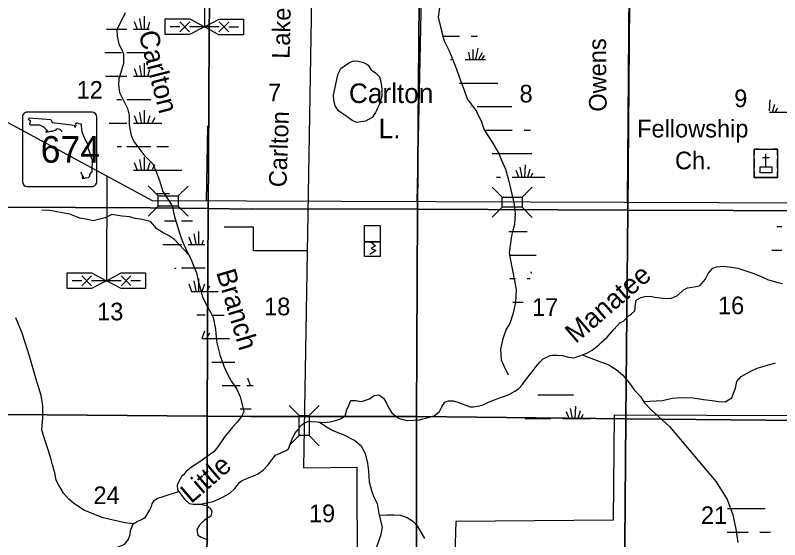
# Model space of a CAD drawing. Extents: x 380424 to 701066, y 1117407 to 1412949.
# Drawn here: x 569307 to 588826, y 1217069 to 1230454 of the extents above; entities that cross this region are included whole.
import ezdxf

# ---------------------------------------------------------------- set-up
doc = ezdxf.new("R2010")
doc.units = 0
for name, color, linetype in [('Bridges', 7, 'Continuous'), ('Bridges and Drawbridges Local Roads', 7, 'Continuous'), ('Bridges and Drawbridges State Highways', 7, 'Continuous'), ('Culture', 7, 'Continuous'), ('Culture Text', 7, 'Continuous'), ('Lakes and Ponds', 7, 'Continuous'), ('Lakes and Ponds Text', 7, 'Continuous'), ('Local Roads Improved', 7, 'Continuous'), ('Local Roads Paved', 7, 'Continuous'), ('Local Roads Related Cells', 7, 'Continuous'), ('Local Roads Related Text', 7, 'Continuous'), ('Narrow Canals', 7, 'Continuous'), ('Narrow River Creek and Branch and Slough', 7, 'Continuous'), ('Narrow River Creek and Branch and Slough Text', 7, 'Continuous'), ('Roadshilelds State Highways', 7, 'Continuous'), ('Section Lines', 7, 'Continuous'), ('Section Numbers', 7, 'Continuous'), ('State Routes Highway Center Lines', 7, 'Continuous'), ('Swamps', 7, 'Continuous'), ('Township  and Range lines', 7, 'Continuous')]:
    doc.layers.add(name, color=color, linetype=linetype)

msp = doc.modelspace()

# ---------------------------------------------------------------- linework, layer by layer
at = {"layer": 'Bridges'}
msp.add_line((576554, 1219728), (576296, 1219473), dxfattribs=at)
at = {"layer": 'Bridges and Drawbridges Local Roads'}
for p, q in [((576557, 1220240), (576302, 1220497)), ((576813, 1220239), (577070, 1220493)), ((576810, 1219727), (577064, 1219469))]:
    msp.add_line(p, q, dxfattribs=at)
msp.add_lwpolyline([(576554, 1219728), (576557, 1220240), (576813, 1220239), (576810, 1219727)], close=True, dxfattribs=at)
at = {"layer": 'Bridges and Drawbridges State Highways'}
for p, q in [((572955, 1225842), (572699, 1226099)), ((573467, 1225842), (573723, 1226097)), ((581739, 1225813), (581484, 1226070)), ((582251, 1225810), (582508, 1226065)), ((572954, 1225586), (572698, 1225331)), ((573466, 1225586), (573722, 1225329)), ((581737, 1225557), (581480, 1225302)), ((582249, 1225554), (582504, 1225297))]:
    msp.add_line(p, q, dxfattribs=at)
for points in [[(572955, 1225842), (573467, 1225842), (573466, 1225586), (572954, 1225586)], [(581739, 1225813), (582251, 1225810), (582249, 1225554), (581737, 1225557)]]:
    msp.add_lwpolyline(points, close=True, dxfattribs=at)
at = {"layer": 'Culture'}
for p, q in [((588173, 1227034), (588173, 1226884)), ((588293, 1227034), (588173, 1227034)), ((588383, 1227034), (588563, 1227034)), ((588773, 1227034), (588653, 1227034)), ((588773, 1226884), (588773, 1227034)), ((588173, 1226794), (588173, 1226554)), ((588383, 1226824), (588563, 1226824)), ((588473, 1226584), (588473, 1226914)), ((588773, 1226554), (588773, 1226794)), ((588173, 1226464), (588173, 1226314)), ((588773, 1226314), (588773, 1226464)), ((588173, 1226314), (588773, 1226314)), ((578226, 1224297), (578226, 1224668)), ((578226, 1224668), (578626, 1224668)), ((578626, 1224668), (578626, 1224297)), ((578626, 1224297), (578226, 1224297))]:
    msp.add_line(p, q, dxfattribs=at)
for points in [[(588173, 1227034), (588773, 1227034), (588773, 1226314), (588173, 1226314)], [(588323, 1226584), (588623, 1226584), (588623, 1226434), (588323, 1226434)], [(578626, 1224668), (578226, 1224668), (578226, 1225087), (578626, 1225087)]]:
    msp.add_lwpolyline(points, close=True, dxfattribs=at)
msp.add_lwpolyline([(578382, 1224668), (578503, 1224574), (578391, 1224506), (578511, 1224447), (578356, 1224347)], dxfattribs=at)
at = {"layer": 'Lakes and Ponds'}
msp.add_lwpolyline([(578506, 1227976), (578505, 1227974), (578416, 1227848), (578248, 1227749), (578022, 1227722), (577906, 1227770), (577744, 1227885), (577570, 1228011), (577476, 1228142), (577439, 1228284), (577434, 1228415), (577460, 1228536), (577518, 1228814), (577555, 1228956), (577618, 1229098), (577702, 1229156), (577843, 1229245), (577943, 1229292), (578059, 1229287), (578195, 1229250), (578284, 1229203), (578316, 1229177), (578395, 1229066), (578505, 1228982), (578599, 1228893), (578610, 1228885)], dxfattribs=at)
msp.add_spline([(578610, 1228885), (578663, 1228397), (578506, 1227976)], degree=3, dxfattribs=at)
at = {"layer": 'Local Roads Improved'}
msp.add_line((574192, 1225711), (574222, 1227633), dxfattribs=at)
for points in [[(574168, 1234761), (574134, 1230158)], [(576757, 1224443), (575392, 1224441), (575391, 1225044), (574642, 1225050)]]:
    msp.add_lwpolyline(points, dxfattribs=at)
at = {"layer": 'Local Roads Paved'}
msp.add_line((571645, 1226344), (571632, 1223677), dxfattribs=at)
for points in [[(576809, 1246604), (576867, 1230903), (576662, 1218901), (578027, 1218917), (578037, 1216197), (580511, 1216138)], [(584939, 1225673), (585048, 1239741)], [(579568, 1225692), (579680, 1230941), (579637, 1236122), (576848, 1236202)], [(594146, 1225641), (594030, 1220213), (584600, 1220250), (584573, 1217567), (580552, 1217530), (580478, 1214990), (581912, 1214974), (581785, 1204105)]]:
    msp.add_lwpolyline(points, dxfattribs=at)
at = {"layer": 'Local Roads Related Cells'}
for p, q in [((573133, 1229963), (573135, 1230363)), ((573135, 1230363), (573760, 1230360)), ((573508, 1230036), (573760, 1230285)), ((573758, 1230035), (573510, 1230286)), ((573760, 1230360), (574134, 1230158)), ((574134, 1230158), (574510, 1230356)), ((574508, 1230031), (574760, 1230280)), ((574510, 1230356), (575135, 1230353)), ((574758, 1230032), (574510, 1230283)), ((575135, 1230353), (575133, 1229953)), ((573509, 1230161), (573259, 1230162)), ((574134, 1230158), (573758, 1229960)), ((574509, 1230156), (573759, 1230160)), ((574508, 1229956), (574134, 1230158)), ((575009, 1230154), (574759, 1230155)), ((573758, 1229960), (573133, 1229963)), ((575133, 1229953), (574508, 1229956)), ((570632, 1223877), (571257, 1223877)), ((570632, 1223477), (570632, 1223877)), ((571257, 1223877), (571632, 1223677)), ((571632, 1223677), (572007, 1223877)), ((572007, 1223877), (572632, 1223877)), ((572632, 1223877), (572632, 1223477)), ((571007, 1223677), (570757, 1223677)), ((571007, 1223552), (571257, 1223802)), ((571257, 1223552), (571007, 1223802)), ((571632, 1223677), (571257, 1223477)), ((572007, 1223677), (571257, 1223677)), ((572007, 1223477), (571632, 1223677)), ((572257, 1223555), (572007, 1223805)), ((572007, 1223552), (572257, 1223802)), ((572507, 1223677), (572257, 1223677)), ((571257, 1223477), (570632, 1223477)), ((572632, 1223477), (572007, 1223477))]:
    msp.add_line(p, q, dxfattribs=at)
at = {"layer": 'Narrow Canals'}
msp.add_lwpolyline([(580156, 1230771), (580104, 1230404), (580161, 1230157), (580256, 1229800), (580382, 1229543), (580497, 1229275), (580576, 1229076), (580644, 1228881), (580765, 1228545), (580844, 1228325), (581075, 1228015), (581211, 1227732), (581280, 1227532), (581485, 1227217), (581653, 1226928), (581716, 1226776), (581826, 1226529), (581899, 1226251), (581973, 1225925), (582036, 1225668), (582067, 1225406), (582057, 1225112), (581999, 1224928), (581973, 1224828), (581920, 1224387), (581968, 1224109), (582010, 1223894), (582094, 1223453), (582078, 1223122), (582015, 1222822), (581931, 1222591), (581842, 1222439), (581752, 1222198), (581700, 1221930), (581716, 1221657), (581784, 1221510), (581894, 1221274)], dxfattribs=at)
at = {"layer": 'Narrow River Creek and Branch and Slough'}
for points in [[(572112, 1230519), (571996, 1230266), (571901, 1230093), (571907, 1229924), (571954, 1229719), (572012, 1229604), (572070, 1229467), (572070, 1229225), (572028, 1229078), (571954, 1228831), (571944, 1228673), (571965, 1228484), (572049, 1228316), (572175, 1228079), (572212, 1227906), (572217, 1227658), (572264, 1227385), (572333, 1227233), (572590, 1226891), (572822, 1226660), (572911, 1226444), (572985, 1226239), (573073, 1225955), (573311, 1225587), (573317, 1225561), (573354, 1225387), (573390, 1225256), (573459, 1225035), (573527, 1224825), (573580, 1224683), (573690, 1224431), (573790, 1224241), (573853, 1224089), (573932, 1223879), (573979, 1223679), (574032, 1223463), (574090, 1223258), (574216, 1223011), (574295, 1222874), (574358, 1222738), (574416, 1222443), (574437, 1222228), (574452, 1222096), (574526, 1221791), (574636, 1221497), (574715, 1221308), (574826, 1221103), (574962, 1220913), (575052, 1220714), (575120, 1220451), (575141, 1220330), (575083, 1220214), (574973, 1220072), (574852, 1219941), (574752, 1219815), (574663, 1219709), (574568, 1219567), (574479, 1219436), (574373, 1219310), (574263, 1219236), (574116, 1219126), (573995, 1219042), (573879, 1218968), (573795, 1218916), (573674, 1218810), (573601, 1218726), (573559, 1218689), (573480, 1218553), (573438, 1218458), (573448, 1218342), (573522, 1218237), (573627, 1218106), (573743, 1217995), (573848, 1217974), (573958, 1217974), (574069, 1217985), (574195, 1218011), (574363, 1218048), (574515, 1218111), (574636, 1218169), (574784, 1218253), (574915, 1218379), (575031, 1218532), (575099, 1218579), (575278, 1218658), (575493, 1218742), (575635, 1218847), (575756, 1218968), (575952, 1219228), (576209, 1219339), (576286, 1219387), (576365, 1219621), (576445, 1219783), (576551, 1219902)], [(573737, 1224341), (573369, 1224732), (573217, 1224837), (573086, 1224900), (572918, 1225000), (572760, 1225189), (572650, 1225220), (572503, 1225247), (572372, 1225268), (572225, 1225309), (572026, 1225325), (571773, 1225370), (571605, 1225283), (571293, 1225206), (571152, 1225238), (570958, 1225275), (570700, 1225374), (570501, 1225416), (570328, 1225443), (570186, 1225469), (569987, 1225479)], [(576811, 1220092), (576856, 1220090), (577019, 1220074), (577198, 1220063), (577350, 1220079), (577487, 1220111), (577608, 1220153), (577729, 1220232), (577776, 1220384), (577808, 1220463), (577871, 1220626), (578002, 1220621), (578144, 1220600), (578355, 1220668), (578470, 1220752), (578591, 1220768), (578712, 1220684), (578786, 1220552), (578838, 1220442), (578922, 1220310), (579064, 1220190), (579138, 1220158), (579322, 1220111), (579485, 1220121), (579627, 1220132), (579853, 1220190), (580000, 1220232), (580137, 1220342), (580168, 1220389), (580200, 1220458), (580226, 1220505), (580279, 1220579), (580305, 1220600), (580368, 1220610), (580489, 1220610), (580584, 1220584), (580720, 1220537), (580815, 1220500), (580920, 1220458), (581010, 1220458), (581157, 1220489), (581272, 1220521), (581409, 1220584), (581541, 1220642), (581667, 1220689), (581851, 1220752), (581940, 1220789), (582061, 1220862), (582156, 1220920), (582261, 1221031), (582313, 1221110), (582429, 1221262), (582540, 1221399), (582597, 1221483), (582697, 1221599), (582787, 1221683), (582944, 1221762), (582965, 1221772), (583028, 1221777), (583134, 1221783), (583281, 1221772), (583433, 1221725), (583565, 1221714), (583696, 1221751), (583817, 1221798), (583917, 1221840), (584038, 1221909), (584206, 1222045), (584274, 1222109), (584411, 1222229), (584595, 1222440), (584742, 1222603), (584848, 1222655), (584968, 1222787), (585042, 1222834), (585126, 1222913), (585142, 1223071), (585163, 1223181), (585279, 1223249), (585379, 1223276), (585520, 1223281), (585641, 1223260), (585773, 1223244), (585852, 1223234), (586046, 1223228), (586220, 1223302), (586367, 1223449), (586472, 1223497), (586693, 1223528), (586793, 1223554), (586919, 1223707), (586998, 1223865), (587114, 1224001), (587208, 1224033), (587403, 1224049), (587592, 1224022), (587760, 1223996), (587939, 1223938), (588139, 1223875), (588296, 1223812), (588517, 1223707), (588722, 1223649), (588896, 1223612)], [(572317, 1217474), (572100, 1217504), (571927, 1217541), (571733, 1217583), (571549, 1217630), (571061, 1217824), (570961, 1217893), (570799, 1217992), (570678, 1218103), (570536, 1218255), (570416, 1218459), (570347, 1218591), (570316, 1218780), (570258, 1218984), (570216, 1219152), (570127, 1219415), (570080, 1219567), (569985, 1219866), (570006, 1220181), (570011, 1220485), (569964, 1220753), (569833, 1221194), (569681, 1221729), (569481, 1222343), (569324, 1222731)], [(583780, 1221784), (584249, 1221606), (584464, 1221533), (584647, 1221412), (584821, 1221265), (584989, 1221061), (585109, 1220898), (585267, 1220725), (585366, 1220567), (585550, 1220379), (585720, 1220222), (586008, 1219959), (587200, 1218547), (587488, 1218096), (587625, 1217703), (587703, 1217340), (587756, 1216994)], [(585350, 1220593), (585834, 1220625), (586081, 1220683), (586306, 1220699), (586616, 1220688), (586878, 1220651), (587104, 1220625), (587272, 1220594), (587435, 1220588), (587603, 1220693), (587645, 1220809), (587697, 1220940), (587729, 1221103), (587839, 1221239), (588075, 1221360), (588253, 1221449), (588720, 1221580)], [(577072, 1220071), (577252, 1219950), (577399, 1219861), (577541, 1219803), (577677, 1219751), (577977, 1219603), (578134, 1219477), (578244, 1219273), (578302, 1219026), (578328, 1218816), (578344, 1218543), (578402, 1218328), (578465, 1218154), (578549, 1217992), (578591, 1217740), (578675, 1217383), (578633, 1217167), (578512, 1216837)], [(571304, 1216059), (571250, 1216219), (571297, 1216361), (571365, 1216450), (571475, 1216660), (571601, 1216723), (571675, 1216759), (571837, 1216843), (571979, 1216901), (572100, 1216954), (572194, 1217085), (572236, 1217205), (572252, 1217305), (572315, 1217473), (572420, 1217536), (572530, 1217583), (572630, 1217641), (572740, 1217830), (572787, 1217914), (572798, 1217982), (572855, 1218066), (572934, 1218129), (573055, 1218166), (573476, 1218303)], [(573959, 1217974), (574069, 1217970), (574195, 1217943), (574294, 1217865), (574326, 1217791), (574300, 1217671), (574142, 1217566), (574006, 1217434), (573943, 1217329), (573969, 1217188), (574053, 1217135), (574221, 1217067)], [(578601, 1217695), (578794, 1217703), (578972, 1217708), (579135, 1217693), (579314, 1217640), (579455, 1217546), (579566, 1217425), (579755, 1217099)]]:
    msp.add_lwpolyline(points, dxfattribs=at)
msp.add_spline([(576551, 1219902), (576624, 1220005), (576811, 1220092)], degree=3, dxfattribs=at)
at = {"layer": 'Roadshilelds State Highways'}
for p, q in [((571262, 1227981), (569612, 1227981)), ((569487, 1227856), (569487, 1226206)), ((571387, 1226206), (571387, 1227856)), ((569612, 1226081), (571262, 1226081))]:
    msp.add_line(p, q, dxfattribs=at)
for points in [[(570506, 1227482), (570487, 1227507), (570444, 1227543), (570375, 1227553), (570345, 1227540), (570342, 1227510), (570312, 1227514), (570259, 1227484), (570200, 1227484), (570124, 1227464), (570098, 1227471), (570101, 1227514), (570118, 1227484), (570134, 1227500), (570098, 1227543), (570042, 1227586), (570005, 1227616), (569933, 1227649), (569857, 1227652), (569702, 1227649), (569679, 1227665), (569692, 1227751), (569646, 1227794), (569663, 1227834)], [(569663, 1227834), (570216, 1227794), (570246, 1227715), (570810, 1227652), (570823, 1227606), (570846, 1227606), (570863, 1227639), (570853, 1227679), (570872, 1227718), (570922, 1227695), (570988, 1227685), (570988, 1227622), (571008, 1227487), (571041, 1227392), (571110, 1227243), (571156, 1227164), (571182, 1227128), (571163, 1227072), (571189, 1227002), (571222, 1226907), (571245, 1226828), (571271, 1226758), (571271, 1226696), (571265, 1226570), (571261, 1226498), (571258, 1226442), (571245, 1226458), (571228, 1226422), (571205, 1226382), (571205, 1226336), (571166, 1226306), (571123, 1226300), (571087, 1226306), (571074, 1226287), (571031, 1226280), (571011, 1226316), (571021, 1226333), (571034, 1226310), (571050, 1226303), (571050, 1226333), (571014, 1226376), (571001, 1226428), (570978, 1226453)]]:
    msp.add_lwpolyline(points, dxfattribs=at)
for centre, start, end in [((569612, 1227856), 90.0003, 180.0003), ((571262, 1227856), 0.0003, 90.0003), ((569612, 1226206), 180.0003, 270.0003), ((571262, 1226206), 270.0003, 0.0003)]:
    msp.add_arc(centre, 125, start, end, dxfattribs=at)
at = {"layer": 'Section Lines'}
for points in [[(574266, 1230835), (574259, 1229902), (574243, 1226792), (574233, 1225522), (572751, 1225542), (568937, 1225557), (568937, 1226654), (568961, 1230874), (568961, 1230879), (574251, 1230835)], [(579622, 1230836), (579580, 1225506), (575336, 1225512), (575336, 1225505), (574233, 1225522), (574243, 1226792), (574259, 1229902), (574266, 1230835), (575347, 1230830)], [(584988, 1230777), (584947, 1225482), (579594, 1225506), (579580, 1225506), (579622, 1230836), (579679, 1230836)], [(590354, 1230726), (590354, 1230713), (590316, 1225459), (584947, 1225482), (584988, 1230777), (590334, 1230727)], [(574233, 1225522), (574222, 1223917), (574209, 1220222), (569101, 1220261), (568936, 1220264), (568936, 1222834), (568937, 1225557), (572751, 1225542)], [(579580, 1225506), (579577, 1225467), (579552, 1220211), (575325, 1220215), (575318, 1220215), (574209, 1220222), (574222, 1223917), (574233, 1225522), (575336, 1225505), (575336, 1225512)], [(584947, 1225482), (584946, 1225472), (584895, 1220166), (584895, 1220152), (579564, 1220211), (579552, 1220211), (579577, 1225467), (579580, 1225506), (579594, 1225506)], [(590316, 1225459), (590316, 1225426), (590282, 1220107), (590268, 1220107), (584902, 1220152), (584895, 1220152), (584895, 1220166), (584946, 1225472), (584947, 1225482)], [(574209, 1220222), (574204, 1217583), (574191, 1215017), (574188, 1214865), (574090, 1214865), (573003, 1214937), (571287, 1214987), (568959, 1215004), (568935, 1218875), (568936, 1220264), (569101, 1220261)], [(579552, 1220211), (579549, 1214877), (579542, 1214878), (575314, 1214876), (574188, 1214865), (574191, 1215017), (574204, 1217583), (574209, 1220222), (575318, 1220215), (575325, 1220215)], [(584895, 1220152), (584853, 1214848), (584816, 1214848), (579549, 1214877), (579552, 1220211), (579564, 1220211)], [(590282, 1220107), (590282, 1220103), (590192, 1214804), (584853, 1214848), (584895, 1220152), (584902, 1220152), (590268, 1220107)]]:
    msp.add_lwpolyline(points, close=True, dxfattribs=at)
at = {"layer": 'State Routes Highway Center Lines'}
msp.add_lwpolyline([(640551, 1225621), (608969, 1225590), (572811, 1225715), (567889, 1228370), (547875, 1228304), (542500, 1228290), (542132, 1228289), (536228, 1228275), (533934, 1228260), (532069, 1228431), (531223, 1228480), (521382, 1228594), (519319, 1228617), (515590, 1228660)], dxfattribs=at)
at = {"layer": 'Swamps'}
for p, q in [((572343, 1230297), (572415, 1230104)), ((572476, 1230370), (572524, 1230116)), ((572596, 1230430), (572596, 1230104)), ((580879, 1229509), (580917, 1229323)), ((580988, 1229582), (580988, 1229323)), ((581121, 1229618), (581062, 1229323)), ((581230, 1229497), (581136, 1229323)), ((572343, 1229097), (572415, 1228904)), ((572476, 1229170), (572524, 1228916)), ((572596, 1229230), (572596, 1228904)), ((572157, 1228304), (572766, 1228304)), ((588644, 1227983), (588702, 1228187)), ((572476, 1227970), (572524, 1227716)), ((572596, 1228030), (572596, 1227704)), ((588720, 1227983), (588769, 1228092)), ((572343, 1227897), (572415, 1227704)), ((572741, 1227885), (572681, 1227704)), ((572874, 1227837), (572802, 1227716)), ((572325, 1227704), (572925, 1227704)), ((572157, 1227104), (572766, 1227104)), ((572922, 1227102), (573223, 1227102)), ((572476, 1226770), (572524, 1226516)), ((572596, 1226830), (572596, 1226504)), ((572343, 1226697), (572415, 1226504)), ((572741, 1226685), (572681, 1226504)), ((572874, 1226637), (572802, 1226516)), ((582248, 1226323), (582201, 1226578)), ((582319, 1226323), (582336, 1226639)), ((572325, 1226504), (572925, 1226504)), ((582163, 1226323), (582097, 1226495)), ((582395, 1226324), (582454, 1226527)), ((582472, 1226323), (582521, 1226432)), ((573868, 1224873), (573916, 1224619)), ((573989, 1224933), (573989, 1224607)), ((573735, 1224800), (573808, 1224607)), ((573549, 1224007), (574159, 1224007)), ((573868, 1223673), (573916, 1223419)), ((573989, 1223733), (573989, 1223407)), ((574134, 1223588), (574074, 1223407)), ((574267, 1223540), (574194, 1223419)), ((574267, 1222340), (574194, 1222219)), ((575235, 1221200), (575308, 1221007)), ((583448, 1220165), (583383, 1220336)), ((583533, 1220164), (583487, 1220419)), ((583604, 1220164), (583621, 1220480)), ((583681, 1220165), (583739, 1220368)), ((583757, 1220164), (583806, 1220273))]:
    msp.add_line(p, q, dxfattribs=at)
for points in [[(572738, 1230276), (572681, 1230104)], [(571634, 1230104), (572156, 1230104)], [(572325, 1230104), (572726, 1230104)], [(580205, 1229923), (580647, 1229923)], [(580947, 1229923), (581107, 1229923)], [(571595, 1229502), (572022, 1229502)], [(572157, 1229504), (572697, 1229504)], [(580420, 1229323), (580497, 1229323)], [(580797, 1229323), (581317, 1229323)], [(581282, 1229424), (581215, 1229324)], [(571611, 1228904), (572156, 1228904)], [(572325, 1228904), (572771, 1228904)], [(572733, 1229061), (572681, 1228904)], [(580647, 1228723), (581628, 1228723)], [(571903, 1228302), (572022, 1228302)], [(580943, 1228123), (580947, 1228123)], [(581097, 1228123), (581987, 1228123)], [(588569, 1228017), (588584, 1228299)], [(588568, 1227983), (589295, 1227983)], [(571702, 1227704), (572156, 1227704)], [(572925, 1227704), (573045, 1227704)], [(581321, 1227523), (581997, 1227523)], [(582297, 1227523), (582460, 1227523)], [(571908, 1227102), (572022, 1227102)], [(581481, 1226923), (582497, 1226923)], [(572925, 1226504), (573562, 1226504)], [(581592, 1226323), (581697, 1226323)], [(581997, 1226323), (582832, 1226323)], [(572922, 1225902), (573247, 1225902)], [(573114, 1225204), (573414, 1225204)], [(573549, 1225207), (573831, 1225207)], [(588751, 1225061), (588884, 1225061)], [(581907, 1224933), (582376, 1224933)], [(573071, 1224607), (573549, 1224607)], [(573718, 1224607), (574147, 1224607)], [(574107, 1224708), (574074, 1224607)], [(588624, 1224461), (588884, 1224461)], [(581948, 1224333), (582607, 1224333)], [(573372, 1224004), (573414, 1224004)], [(582491, 1223863), (582476, 1223905)], [(581933, 1223733), (582076, 1223733)], [(582376, 1223733), (582454, 1223733)], [(573735, 1223600), (573808, 1223407)], [(573808, 1223407), (574318, 1223407)], [(574318, 1223407), (574491, 1223407)], [(582007, 1223133), (582274, 1223133)], [(573946, 1222807), (574159, 1222807)], [(574314, 1222804), (574639, 1222804)], [(574134, 1222388), (574074, 1222208)], [(574074, 1222207), (574318, 1222207)], [(574318, 1222207), (574780, 1222207)], [(574327, 1221604), (574914, 1221604)], [(574592, 1221007), (575049, 1221007)], [(575218, 1221007), (575382, 1221007)], [(582647, 1220764), (583559, 1220764)], [(575049, 1220407), (575332, 1220407)], [(582328, 1220164), (582983, 1220164)], [(583283, 1220164), (583994, 1220164)], [(587489, 1217864), (588458, 1217864)], [(587486, 1217264), (588019, 1217264)], [(588319, 1217264), (588591, 1217264)]]:
    msp.add_lwpolyline(points, dxfattribs=at)
at = {"layer": 'Township  and Range lines'}
for p, q in [((574266, 1230835), (574259, 1229902)), ((574259, 1229902), (574243, 1226792)), ((574243, 1226792), (574233, 1225522)), ((574233, 1225522), (574222, 1223917)), ((574222, 1223917), (574209, 1220222)), ((574209, 1220222), (574204, 1217583)), ((574204, 1217583), (574191, 1215017))]:
    msp.add_line(p, q, dxfattribs=at)

# ---------------------------------------------------------------- texts
at = {"layer": 'Culture Text'}
for s, p in [('Fellowship', (585184, 1227337)), ('Ch.', (586152, 1226524))]:
    msp.add_text(s, height=450, rotation=0.0003, dxfattribs=at).set_placement(p)
at = {"layer": 'Lakes and Ponds Text'}
for s, p in [('Carlton', (577827, 1228214)), ('L.', (578585, 1227314))]:
    msp.add_text(s, height=500, rotation=0.0003, dxfattribs=at).set_placement(p)
at = {"layer": 'Local Roads Related Text'}
for s, rotation, p in [('Lake', 88.6801, (576311, 1229341)), ('Owens', 90.6331, (584409, 1227996)), ('Carlton', 88.0673, (576230, 1226060))]:
    msp.add_text(s, height=450, rotation=rotation, dxfattribs=at).set_placement(p)
at = {"layer": 'Narrow River Creek and Branch and Slough Text'}
for s, rotation, p in [('Carlton', 284.5111, (572450, 1230000)), ('Manatee', 40.7862, (583615, 1222059)), ('Branch', 286.5111, (574433, 1223896)), ('Little', 40.7861, (573797, 1217976))]:
    msp.add_text(s, height=500, rotation=rotation, dxfattribs=at).set_placement(p)
at = {"layer": 'Roadshilelds State Highways'}
msp.add_text('674', height=680, rotation=0.0003, dxfattribs=at).set_placement((569955, 1226691))
at = {"layer": 'Section Numbers'}
for s, rotation, p in [('12', 0.0003, (570872, 1228325)), ('7', 0.0003, (575762, 1228260)), ('8', 0.0003, (582182, 1228230)), ('9', 0.0003, (587664, 1228109)), ('18', 0.0003, (575660, 1222797)), ('16', 0.0003, (587249, 1222825)), ('13', 0.0003, (571397, 1222668)), ('17', 0.0003, (582502, 1222783)), ('24', 0.0003, (571303, 1217978)), ('19', 0.0002, (576805, 1217516)), ('21', 0.0002, (586814, 1217469))]:
    msp.add_text(s, height=450, rotation=rotation, dxfattribs=at).set_placement(p)

doc.saveas('drawing.dxf')
